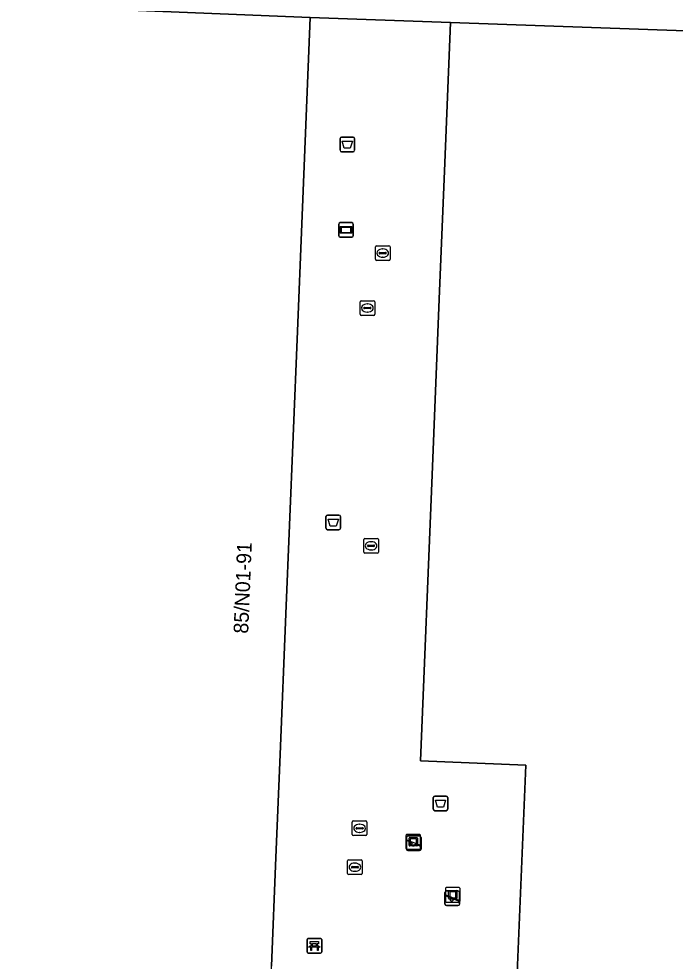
# Model space of a CAD drawing. Extents: x 160888 to 161385, y 386490 to 386908.
# Drawn here: x 161141.4 to 161186.2, y 386769.6 to 386833.9 of the extents above; entities that cross this region are included whole.
import ezdxf

# ---------------------------------------------------------------- set-up
doc = ezdxf.new("R2010")
doc.units = 0
for name, color, linetype in [('IMGEO_Afvalbak', 7, 'Continuous'), ('IMGEO_Bank', 7, 'Continuous'), ('IMGEO_Kolk', 7, 'Continuous'), ('IMGEO_Kunstobject', 7, 'Continuous'), ('IMGEO_Pand', 7, 'Continuous'), ('IMGEO_Pand_nummerreeks', 7, 'Continuous'), ('IMGEO_Reclamebord', 7, 'Continuous'), ('IMGEO_Rioolput', 7, 'Continuous'), ('IMGEO_Speelvoorziening', 7, 'Continuous'), ('IMGEO_Voetgangersgebied_open', 7, 'Continuous'), ('IMGEO_Voetpad_open', 7, 'Continuous')]:
    doc.layers.add(name, color=color, linetype=linetype)

msp = doc.modelspace()

# ---------------------------------------------------------------- linework, layer by layer
at = {"layer": 'IMGEO_Afvalbak'}
for p, q in [((161163.42, 386825.803), (161164.21, 386825.803)), ((161164.21, 386825.803), (161163.42, 386825.803)), ((161163.32, 386824.903), (161163.32, 386825.703)), ((161163.32, 386825.703), (161163.32, 386824.903)), ((161164.31, 386825.703), (161164.31, 386824.903)), ((161164.31, 386824.903), (161164.31, 386825.703)), ((161164.21, 386824.803), (161163.42, 386824.803)), ((161163.42, 386824.803), (161164.21, 386824.803)), ((161162.36, 386799.115), (161162.36, 386799.915)), ((161162.36, 386799.915), (161162.36, 386799.115)), ((161162.46, 386800.015), (161163.25, 386800.015)), ((161163.25, 386800.015), (161162.46, 386800.015)), ((161163.35, 386799.915), (161163.35, 386799.115)), ((161163.35, 386799.115), (161163.35, 386799.915)), ((161163.25, 386799.015), (161162.46, 386799.015)), ((161162.46, 386799.015), (161163.25, 386799.015)), ((161169.786, 386780.845), (161170.576, 386780.845)), ((161170.576, 386780.845), (161169.786, 386780.845)), ((161169.686, 386779.945), (161169.686, 386780.745)), ((161169.686, 386780.745), (161169.686, 386779.945)), ((161170.676, 386780.745), (161170.676, 386779.945)), ((161170.676, 386779.945), (161170.676, 386780.745)), ((161170.576, 386779.845), (161169.786, 386779.845)), ((161169.786, 386779.845), (161170.576, 386779.845))]:
    msp.add_line(p, q, dxfattribs=at)
for points in [[(161163.463, 386825.517), (161164.167, 386825.517), (161164.018, 386825.047), (161163.612, 386825.047), (161163.463, 386825.517)], [(161162.503, 386799.729), (161163.207, 386799.729), (161163.058, 386799.259), (161162.652, 386799.259), (161162.503, 386799.729)], [(161169.829, 386780.559), (161170.533, 386780.559), (161170.384, 386780.089), (161169.978, 386780.089), (161169.829, 386780.559)]]:
    msp.add_lwpolyline(points, dxfattribs=at)
for centre, start, end in [((161163.42, 386825.703), 90, 180), ((161163.42, 386825.703), 90, 180), ((161164.21, 386825.703), 0, 90), ((161164.21, 386825.703), 360, 90), ((161163.42, 386824.903), 180, 270), ((161163.42, 386824.903), 180, 270), ((161164.21, 386824.903), 270, 0), ((161164.21, 386824.903), 270, 0), ((161162.46, 386799.915), 90, 180), ((161162.46, 386799.915), 90, 180), ((161163.25, 386799.915), 0, 90), ((161163.25, 386799.915), 360, 90), ((161162.46, 386799.115), 180, 270), ((161162.46, 386799.115), 180, 270), ((161163.25, 386799.115), 270, 0), ((161163.25, 386799.115), 270, 0), ((161169.786, 386780.745), 90, 180), ((161169.786, 386780.745), 90, 180), ((161170.576, 386780.745), 0, 90), ((161170.576, 386780.745), 360, 90), ((161169.786, 386779.945), 180, 270), ((161169.786, 386779.945), 180, 270), ((161170.576, 386779.945), 270, 0), ((161170.576, 386779.945), 270, 0)]:
    msp.add_arc(centre, 0.1, start, end, dxfattribs=at)
at = {"layer": 'IMGEO_Bank'}
for p, q in [((161161.148, 386771.132), (161161.989, 386771.132)), ((161161.989, 386771.132), (161161.148, 386771.132)), ((161161.073, 386770.207), (161161.073, 386771.048)), ((161161.073, 386771.048), (161161.073, 386770.207)), ((161161.77, 386770.53), (161161.377, 386770.53)), ((161161.382, 386770.638), (161161.382, 386770.744)), ((161161.426, 386770.744), (161161.426, 386770.638)), ((161161.714, 386770.75), (161161.432, 386770.75)), ((161161.432, 386770.632), (161161.714, 386770.632)), ((161161.72, 386770.638), (161161.72, 386770.744)), ((161161.764, 386770.744), (161161.764, 386770.638)), ((161162.073, 386771.057), (161162.073, 386770.216)), ((161162.073, 386770.216), (161162.073, 386771.057)), ((161161.998, 386770.132), (161161.157, 386770.132)), ((161161.157, 386770.132), (161161.998, 386770.132))]:
    msp.add_line(p, q, dxfattribs=at)
for points in [[(161161.32, 386770.53), (161161.178, 386770.53), (161161.29, 386770.632), (161161.376, 386770.632)], [(161161.376, 386770.75), (161161.29, 386770.75), (161161.29, 386770.911), (161161.853, 386770.911), (161161.853, 386770.75), (161161.77, 386770.75)], [(161161.37, 386770.523), (161161.37, 386770.316), (161161.327, 386770.316), (161161.327, 386770.523)], [(161161.77, 386770.632), (161161.853, 386770.632), (161161.965, 386770.53), (161161.826, 386770.53)], [(161161.82, 386770.523), (161161.82, 386770.316), (161161.776, 386770.316), (161161.776, 386770.523)]]:
    msp.add_lwpolyline(points, dxfattribs=at)
for centre, radius, start, end in [((161161.151, 386771.054), 0.0779, 92.4484, 184.28452), ((161161.151, 386771.054), 0.0779, 92.4484, 184.28452), ((161161.995, 386771.054), 0.0779, 2.4484, 94.28452), ((161161.995, 386771.054), 0.0779, 2.4484, 94.28452), ((161161.32, 386770.523), 0.00671, 2.89567, 87.10433), ((161161.377, 386770.523), 0.00671, 92.89567, 177.10433), ((161161.375, 386770.743), 0.00671, 2.89567, 87.10433), ((161161.375, 386770.639), 0.00671, 272.89567, 357.10433), ((161161.432, 386770.743), 0.00671, 92.89567, 177.10433), ((161161.432, 386770.639), 0.00671, 182.89567, 267.10433), ((161161.714, 386770.743), 0.00671, 2.89567, 87.10433), ((161161.714, 386770.639), 0.00671, 272.89567, 357.10433), ((161161.771, 386770.743), 0.00671, 92.89567, 177.10433), ((161161.771, 386770.639), 0.00671, 182.89567, 267.10433), ((161161.769, 386770.523), 0.00671, 2.89567, 87.10433), ((161161.826, 386770.523), 0.00671, 92.89567, 177.10433), ((161161.151, 386770.21), 0.0779, 182.4484, 274.28452), ((161161.151, 386770.21), 0.0779, 182.4484, 274.28452), ((161161.995, 386770.21), 0.0779, 272.4484, 4.28452), ((161161.995, 386770.21), 0.0779, 272.4484, 4.28452)]:
    msp.add_arc(centre, radius, start, end, dxfattribs=at)
at = {"layer": 'IMGEO_Kolk'}
for p, q in [((161165.734, 386817.465), (161165.734, 386818.317)), ((161165.809, 386818.391), (161166.661, 386818.391)), ((161166.222, 386818.171), (161166.247, 386818.171)), ((161166.735, 386818.317), (161166.735, 386817.465)), ((161165.993, 386817.885), (161165.993, 386817.897)), ((161166.431, 386817.848), (161166.033, 386817.848)), ((161166.036, 386817.934), (161166.434, 386817.934)), ((161166.245, 386817.611), (161166.22, 386817.611)), ((161166.477, 386817.897), (161166.477, 386817.885)), ((161166.661, 386817.391), (161165.809, 386817.391)), ((161164.941, 386797.493), (161164.941, 386798.345)), ((161165.016, 386798.419), (161165.868, 386798.419)), ((161165.429, 386798.199), (161165.454, 386798.199)), ((161165.942, 386798.345), (161165.942, 386797.493)), ((161165.2, 386797.913), (161165.2, 386797.925)), ((161165.638, 386797.876), (161165.24, 386797.876)), ((161165.243, 386797.962), (161165.641, 386797.962)), ((161165.452, 386797.639), (161165.427, 386797.639)), ((161165.684, 386797.925), (161165.684, 386797.913)), ((161165.868, 386797.419), (161165.016, 386797.419)), ((161164.159, 386778.217), (161164.159, 386779.069)), ((161164.234, 386779.143), (161165.086, 386779.143)), ((161164.647, 386778.923), (161164.672, 386778.923)), ((161165.16, 386779.069), (161165.16, 386778.217)), ((161164.418, 386778.637), (161164.418, 386778.649)), ((161164.856, 386778.6), (161164.458, 386778.6)), ((161164.461, 386778.686), (161164.859, 386778.686)), ((161164.67, 386778.363), (161164.645, 386778.363)), ((161164.902, 386778.649), (161164.902, 386778.637)), ((161165.086, 386778.143), (161164.234, 386778.143))]:
    msp.add_line(p, q, dxfattribs=at)
for points in [[(161165.734, 386817.465), (161165.734, 386818.317)], [(161165.809, 386818.391), (161166.661, 386818.391)], [(161166.735, 386818.317), (161166.735, 386817.465)], [(161166.661, 386817.391), (161165.809, 386817.391)], [(161164.941, 386797.493), (161164.941, 386798.345)], [(161165.016, 386798.419), (161165.868, 386798.419)], [(161165.942, 386798.345), (161165.942, 386797.493)], [(161165.868, 386797.419), (161165.016, 386797.419)], [(161164.159, 386778.217), (161164.159, 386779.069)], [(161164.234, 386779.143), (161165.086, 386779.143)], [(161165.16, 386779.069), (161165.16, 386778.217)], [(161165.086, 386778.143), (161164.234, 386778.143)]]:
    msp.add_lwpolyline(points, dxfattribs=at)
for centre, radius, start, end in [((161165.811, 386818.315), 0.0765, 91.55205, 178.44795), ((161165.811, 386818.315), 0.0765, 91.55205, 178.44795), ((161166.659, 386818.315), 0.0765, 1.55205, 88.44795), ((161166.659, 386818.315), 0.0765, 1.55205, 88.44795), ((161165.811, 386817.467), 0.0765, 181.55205, 268.44795), ((161165.811, 386817.467), 0.0765, 181.55205, 268.44795), ((161166.033, 386817.894), 0.0403, 85.87752, 175.75265), ((161166.03, 386817.884), 0.0366, 178.93798, 274.71019), ((161166.434, 386817.891), 0.043, 264.86636, 352.45326), ((161166.438, 386817.896), 0.0386, 1.73085, 96.63898), ((161166.659, 386817.467), 0.0765, 271.55205, 358.44795), ((161166.659, 386817.467), 0.0765, 271.55205, 358.44795), ((161165.018, 386798.343), 0.0765, 91.55205, 178.44795), ((161165.018, 386798.343), 0.0765, 91.55205, 178.44795), ((161165.866, 386798.343), 0.0765, 1.55205, 88.44795), ((161165.866, 386798.343), 0.0765, 1.55205, 88.44795), ((161165.018, 386797.495), 0.0765, 181.55205, 268.44795), ((161165.018, 386797.495), 0.0765, 181.55205, 268.44795), ((161165.24, 386797.922), 0.0403, 85.87752, 175.75265), ((161165.237, 386797.912), 0.0366, 178.93798, 274.71019), ((161165.641, 386797.919), 0.043, 264.86636, 352.45326), ((161165.645, 386797.924), 0.0386, 1.73085, 96.63898), ((161165.866, 386797.495), 0.0765, 271.55205, 358.44795), ((161165.866, 386797.495), 0.0765, 271.55205, 358.44795), ((161164.236, 386779.067), 0.0765, 91.55205, 178.44795), ((161164.236, 386779.067), 0.0765, 91.55205, 178.44795), ((161165.084, 386779.067), 0.0765, 1.55205, 88.44795), ((161165.084, 386779.067), 0.0765, 1.55205, 88.44795), ((161164.236, 386778.219), 0.0765, 181.55205, 268.44795), ((161164.236, 386778.219), 0.0765, 181.55205, 268.44795), ((161164.458, 386778.646), 0.0403, 85.87752, 175.75265), ((161164.455, 386778.636), 0.0366, 178.93798, 274.71019), ((161164.859, 386778.643), 0.043, 264.86636, 352.45326), ((161164.863, 386778.648), 0.0386, 1.73085, 96.63898), ((161165.084, 386778.219), 0.0765, 271.55205, 358.44795), ((161165.084, 386778.219), 0.0765, 271.55205, 358.44795)]:
    msp.add_arc(centre, radius, start, end, dxfattribs=at)
for centre, major_axis, ratio, start_param, end_param in [((161166.221, 386817.891), (-0.387, 0.002), 0.722429, 4.712389, 7.853982), ((161166.246, 386817.891), (-0.39, 0.002), 0.717154, 1.570796, 4.712389), ((161165.428, 386797.919), (-0.387, 0.002), 0.722429, 4.712389, 7.853982), ((161165.453, 386797.919), (-0.39, 0.002), 0.717154, 1.570796, 4.712389), ((161164.646, 386778.643), (-0.387, 0.002), 0.722429, 4.712389, 7.853982), ((161164.671, 386778.643), (-0.39, 0.002), 0.717154, 1.570796, 4.712389)]:
    msp.add_ellipse(centre, major_axis=major_axis, ratio=ratio, start_param=start_param, end_param=end_param, dxfattribs=at)
at = {"layer": 'IMGEO_Kunstobject'}
for p, q in [((161168.739, 386778.223), (161167.898, 386778.223)), ((161168.739, 386778.223), (161167.898, 386778.223)), ((161167.823, 386778.139), (161167.823, 386777.298)), ((161167.823, 386778.139), (161167.823, 386777.298)), ((161168.037, 386777.487), (161168.037, 386777.961)), ((161168.087, 386778.011), (161168.561, 386778.011)), ((161168.117, 386777.911), (161168.117, 386777.537)), ((161168.511, 386777.931), (161168.137, 386777.931)), ((161168.531, 386777.537), (161168.531, 386777.911)), ((161168.611, 386777.961), (161168.611, 386777.487)), ((161168.823, 386777.307), (161168.823, 386778.148)), ((161168.823, 386777.307), (161168.823, 386778.148)), ((161167.907, 386777.223), (161168.748, 386777.223)), ((161167.907, 386777.223), (161168.748, 386777.223)), ((161168.561, 386777.437), (161168.087, 386777.437)), ((161168.137, 386777.517), (161168.511, 386777.517)), ((161170.514, 386774.521), (161170.514, 386773.68)), ((161170.514, 386774.521), (161170.514, 386773.68)), ((161171.43, 386774.605), (161170.589, 386774.605)), ((161171.43, 386774.605), (161170.589, 386774.605)), ((161170.728, 386773.869), (161170.728, 386774.343)), ((161170.778, 386774.393), (161171.252, 386774.393)), ((161171.302, 386774.343), (161171.302, 386773.869)), ((161171.514, 386773.689), (161171.514, 386774.53)), ((161171.514, 386773.689), (161171.514, 386774.53)), ((161171.252, 386773.819), (161170.778, 386773.819)), ((161170.808, 386774.293), (161170.808, 386773.919)), ((161171.202, 386774.313), (161170.828, 386774.313)), ((161170.828, 386773.899), (161171.202, 386773.899)), ((161171.222, 386773.919), (161171.222, 386774.293)), ((161170.598, 386773.605), (161171.439, 386773.605)), ((161170.598, 386773.605), (161171.439, 386773.605))]:
    msp.add_line(p, q, dxfattribs=at)
for centre, radius, start, end in [((161167.901, 386778.145), 0.0779, 92.4484, 184.28452), ((161167.901, 386778.145), 0.0779, 92.4484, 184.28452), ((161168.745, 386778.145), 0.0779, 2.4484, 94.28452), ((161168.745, 386778.145), 0.0779, 2.4484, 94.28452), ((161168.087, 386777.961), 0.05, 90, 180), ((161168.137, 386777.911), 0.02, 90, 180), ((161168.511, 386777.911), 0.02, 360, 90), ((161168.561, 386777.961), 0.05, 360, 90), ((161167.901, 386777.301), 0.0779, 182.4484, 274.28452), ((161167.901, 386777.301), 0.0779, 182.4484, 274.28452), ((161168.087, 386777.487), 0.05, 180, 270), ((161168.137, 386777.537), 0.02, 180, 270), ((161168.511, 386777.537), 0.02, 270, 0), ((161168.561, 386777.487), 0.05, 270, 0), ((161168.745, 386777.301), 0.0779, 272.4484, 4.28452), ((161168.745, 386777.301), 0.0779, 272.4484, 4.28452), ((161170.592, 386774.527), 0.0779, 92.4484, 184.28452), ((161170.592, 386774.527), 0.0779, 92.4484, 184.28452), ((161170.778, 386774.343), 0.05, 90, 180), ((161171.252, 386774.343), 0.05, 360, 90), ((161171.436, 386774.527), 0.0779, 2.4484, 94.28452), ((161171.436, 386774.527), 0.0779, 2.4484, 94.28452), ((161170.778, 386773.869), 0.05, 180, 270), ((161170.828, 386774.293), 0.02, 90, 180), ((161170.828, 386773.919), 0.02, 180, 270), ((161171.202, 386774.293), 0.02, 360, 90), ((161171.202, 386773.919), 0.02, 270, 0), ((161171.252, 386773.869), 0.05, 270, 0), ((161170.592, 386773.683), 0.0779, 182.4484, 274.28452), ((161170.592, 386773.683), 0.0779, 182.4484, 274.28452), ((161171.436, 386773.683), 0.0779, 272.4484, 4.28452), ((161171.436, 386773.683), 0.0779, 272.4484, 4.28452)]:
    msp.add_arc(centre, radius, start, end, dxfattribs=at)
at = {"layer": 'IMGEO_Pand'}
msp.add_lwpolyline([(161139.487, 386830.001), (161139.114, 386820.799), (161139.102, 386820.494), (161138.818, 386813.477), (161138.527, 386806.308), (161138.037, 386794.207), (161137.648, 386784.596), (161137.363, 386777.579), (161137.063, 386770.156), (161136.569, 386757.969), (161156.498, 386757.182), (161158.228, 386758.915), (161158.648, 386769.233), (161158.95, 386776.656), (161159.236, 386783.673), (161159.627, 386793.285), (161160.119, 386805.384), (161160.411, 386812.554), (161160.709, 386819.875), (161161.282, 386833.963), (161143.958, 386834.674), (161139.684, 386834.849)], close=True, dxfattribs=at)
msp.add_lwpolyline([(161190.117, 386832.93), (161170.867, 386833.628), (161170.475, 386824.04), (161170.096, 386814.751), (161169.606, 386802.752), (161168.81, 386783.258), (161176.001, 386782.954), (161175.409, 386768.77), (161175.112, 386761.653), (161174.808, 386754.38), (161174.625, 386750), (161174.605, 386749.514), (161174.331, 386742.954), (161173.519, 386722.968), (161215.329, 386721.218)], dxfattribs=at)
at = {"layer": 'IMGEO_Reclamebord'}
for p, q in [((161163.239, 386819.071), (161163.239, 386819.871)), ((161163.239, 386819.871), (161163.239, 386819.071)), ((161163.339, 386819.971), (161164.129, 386819.971)), ((161164.129, 386819.971), (161163.339, 386819.971)), ((161164.229, 386819.871), (161164.229, 386819.071)), ((161164.229, 386819.071), (161164.229, 386819.871)), ((161164.129, 386818.971), (161163.339, 386818.971)), ((161163.339, 386818.971), (161164.129, 386818.971))]:
    msp.add_line(p, q, dxfattribs=at)
for points in [[(161163.34, 386819.703), (161164.128, 386819.703), (161164.128, 386819.239), (161163.34, 386819.239), (161163.34, 386819.703)], [(161163.405, 386819.638), (161163.405, 386819.304), (161164.063, 386819.304), (161164.063, 386819.638), (161163.405, 386819.638)]]:
    msp.add_lwpolyline(points, dxfattribs=at)
for centre, start, end in [((161163.339, 386819.871), 90, 180), ((161163.339, 386819.871), 90, 180), ((161164.129, 386819.871), 0, 90), ((161164.129, 386819.871), 360, 90), ((161163.339, 386819.071), 180, 270), ((161163.339, 386819.071), 180, 270), ((161164.129, 386819.071), 270, 0), ((161164.129, 386819.071), 270, 0)]:
    msp.add_arc(centre, 0.1, start, end, dxfattribs=at)
at = {"layer": 'IMGEO_Rioolput'}
for p, q in [((161164.687, 386813.716), (161164.687, 386814.568)), ((161164.762, 386814.642), (161165.614, 386814.642)), ((161165.175, 386814.422), (161165.2, 386814.422)), ((161165.688, 386814.568), (161165.688, 386813.716)), ((161165.614, 386813.642), (161164.762, 386813.642)), ((161164.946, 386814.136), (161164.946, 386814.148)), ((161165.384, 386814.099), (161164.986, 386814.099)), ((161164.989, 386814.185), (161165.387, 386814.185)), ((161165.198, 386813.862), (161165.173, 386813.862)), ((161165.43, 386814.148), (161165.43, 386814.136)), ((161163.839, 386775.562), (161163.839, 386776.414)), ((161163.914, 386776.488), (161164.766, 386776.488)), ((161164.327, 386776.268), (161164.352, 386776.268)), ((161164.84, 386776.414), (161164.84, 386775.562)), ((161164.098, 386775.982), (161164.098, 386775.994)), ((161164.536, 386775.945), (161164.138, 386775.945)), ((161164.141, 386776.031), (161164.539, 386776.031)), ((161164.35, 386775.708), (161164.325, 386775.708)), ((161164.582, 386775.994), (161164.582, 386775.982)), ((161164.766, 386775.488), (161163.914, 386775.488))]:
    msp.add_line(p, q, dxfattribs=at)
for points in [[(161164.687, 386813.716), (161164.687, 386814.568)], [(161164.762, 386814.642), (161165.614, 386814.642)], [(161165.688, 386814.568), (161165.688, 386813.716)], [(161165.614, 386813.642), (161164.762, 386813.642)], [(161163.839, 386775.562), (161163.839, 386776.414)], [(161163.914, 386776.488), (161164.766, 386776.488)], [(161164.84, 386776.414), (161164.84, 386775.562)], [(161164.766, 386775.488), (161163.914, 386775.488)]]:
    msp.add_lwpolyline(points, dxfattribs=at)
for centre, radius, start, end in [((161164.764, 386814.566), 0.0765, 91.55205, 178.44795), ((161164.764, 386814.566), 0.0765, 91.55205, 178.44795), ((161165.612, 386814.566), 0.0765, 1.55205, 88.44795), ((161165.612, 386814.566), 0.0765, 1.55205, 88.44795), ((161164.764, 386813.718), 0.0765, 181.55205, 268.44795), ((161164.764, 386813.718), 0.0765, 181.55205, 268.44795), ((161164.986, 386814.145), 0.0403, 85.87752, 175.75265), ((161164.983, 386814.135), 0.0366, 178.93798, 274.71019), ((161165.387, 386814.142), 0.043, 264.86636, 352.45326), ((161165.391, 386814.147), 0.0386, 1.73085, 96.63898), ((161165.612, 386813.718), 0.0765, 271.55205, 358.44795), ((161165.612, 386813.718), 0.0765, 271.55205, 358.44795), ((161163.916, 386776.412), 0.0765, 91.55205, 178.44795), ((161163.916, 386776.412), 0.0765, 91.55205, 178.44795), ((161164.764, 386776.412), 0.0765, 1.55205, 88.44795), ((161164.764, 386776.412), 0.0765, 1.55205, 88.44795), ((161164.138, 386775.991), 0.0403, 85.87752, 175.75265), ((161164.135, 386775.981), 0.0366, 178.93798, 274.71019), ((161164.539, 386775.988), 0.043, 264.86636, 352.45326), ((161164.543, 386775.993), 0.0386, 1.73085, 96.63898), ((161163.916, 386775.564), 0.0765, 181.55205, 268.44795), ((161163.916, 386775.564), 0.0765, 181.55205, 268.44795), ((161164.764, 386775.564), 0.0765, 271.55205, 358.44795), ((161164.764, 386775.564), 0.0765, 271.55205, 358.44795)]:
    msp.add_arc(centre, radius, start, end, dxfattribs=at)
for centre, major_axis, ratio, start_param, end_param in [((161165.174, 386814.142), (-0.387, 0.002), 0.722429, 4.712389, 7.853982), ((161165.199, 386814.142), (-0.39, 0.002), 0.717154, 1.570796, 4.712389), ((161164.326, 386775.988), (-0.387, 0.002), 0.722429, 4.712389, 7.853982), ((161164.351, 386775.988), (-0.39, 0.002), 0.717154, 1.570796, 4.712389)]:
    msp.add_ellipse(centre, major_axis=major_axis, ratio=ratio, start_param=start_param, end_param=end_param, dxfattribs=at)
at = {"layer": 'IMGEO_Speelvoorziening'}
for p, q in [((161167.86, 386777.22), (161167.86, 386778.02)), ((161167.86, 386778.02), (161167.86, 386777.22)), ((161168.243, 386777.648), (161167.904, 386777.785)), ((161167.929, 386777.845), (161168.805, 386777.492)), ((161167.96, 386778.12), (161168.75, 386778.12)), ((161168.75, 386778.12), (161167.96, 386778.12)), ((161168.781, 386777.432), (161168.441, 386777.569)), ((161168.85, 386778.02), (161168.85, 386777.22)), ((161168.85, 386777.22), (161168.85, 386778.02)), ((161168.75, 386777.12), (161167.96, 386777.12)), ((161167.96, 386777.12), (161168.75, 386777.12)), ((161170.583, 386774.368), (161171.373, 386774.368)), ((161171.373, 386774.368), (161170.583, 386774.368)), ((161170.483, 386773.468), (161170.483, 386774.268)), ((161170.483, 386774.268), (161170.483, 386773.468)), ((161170.866, 386773.896), (161170.527, 386774.033)), ((161170.552, 386774.093), (161171.428, 386773.74)), ((161171.404, 386773.68), (161171.064, 386773.817)), ((161171.473, 386774.268), (161171.473, 386773.468)), ((161171.473, 386773.468), (161171.473, 386774.268)), ((161171.373, 386773.368), (161170.583, 386773.368)), ((161170.583, 386773.368), (161171.373, 386773.368))]:
    msp.add_line(p, q, dxfattribs=at)
for centre, radius, start, end in [((161167.96, 386778.02), 0.1, 90, 180), ((161167.96, 386778.02), 0.1, 90, 180), ((161167.917, 386777.815), 0.0327, 68.07798, 248.07798), ((161168.322, 386777.558), 0.12, 130.99278, 5.16318), ((161168.75, 386778.02), 0.1, 0, 90), ((161168.75, 386778.02), 0.1, 360, 90), ((161167.96, 386777.22), 0.1, 180, 270), ((161167.96, 386777.22), 0.1, 180, 270), ((161168.75, 386777.22), 0.1, 270, 0), ((161168.75, 386777.22), 0.1, 270, 0), ((161168.793, 386777.462), 0.0327, 248.07798, 68.07798), ((161170.583, 386774.268), 0.1, 90, 180), ((161170.583, 386774.268), 0.1, 90, 180), ((161171.373, 386774.268), 0.1, 0, 90), ((161171.373, 386774.268), 0.1, 360, 90), ((161170.54, 386774.063), 0.0327, 68.07798, 248.07798), ((161170.945, 386773.806), 0.12, 130.99278, 5.16318), ((161171.416, 386773.71), 0.0327, 248.07798, 68.07798), ((161170.583, 386773.468), 0.1, 180, 270), ((161170.583, 386773.468), 0.1, 180, 270), ((161171.373, 386773.468), 0.1, 270, 0), ((161171.373, 386773.468), 0.1, 270, 0)]:
    msp.add_arc(centre, radius, start, end, dxfattribs=at)
at = {"layer": 'IMGEO_Voetgangersgebied_open'}
msp.add_lwpolyline([(161128.442, 386835.301), (161139.684, 386834.849), (161143.958, 386834.674), (161161.282, 386833.963), (161170.867, 386833.628), (161190.117, 386832.93), (161199.627, 386832.585), (161199.621, 386832.448), (161201.804, 386832.359), (161216.339, 386831.766), (161223.504, 386831.473), (161238.036, 386830.88), (161252.467, 386830.291), (161259.736, 386829.994), (161269.188, 386829.608), (161281.723, 386829.096), (161281.825, 386831.496), (161282.087, 386837.641), (161282.13, 386838.652), (161282.19, 386840.045), (161203.707, 386843.159), (161196.993, 386842.62), (161194.586, 386842.427), (161120.067, 386845.369)], dxfattribs=at)
at = {"layer": 'IMGEO_Voetpad_open'}
msp.add_lwpolyline([(161175.409, 386768.77), (161176.001, 386782.954), (161168.81, 386783.258), (161169.606, 386802.752), (161170.096, 386814.751), (161170.475, 386824.04), (161170.867, 386833.628), (161161.282, 386833.963), (161160.709, 386819.875), (161160.411, 386812.554), (161160.119, 386805.384), (161159.627, 386793.285), (161159.236, 386783.673), (161158.95, 386776.656), (161158.648, 386769.233)], dxfattribs=at)

# ---------------------------------------------------------------- texts
at = {"layer": 'IMGEO_Pand_nummerreeks'}
msp.add_text('85/N01-91', height=1, rotation=87.66969, dxfattribs=at).set_placement((161157.049, 386791.91))

doc.saveas('drawing.dxf')
